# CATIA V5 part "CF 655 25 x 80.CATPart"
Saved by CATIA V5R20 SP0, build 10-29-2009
Part number: CF 655 25 x 80
Definition: NONE
Nomenclature: CF 655 25 x 80
Source: Unknown
Description: CF 655 25 x 80
Bounding box of the stored display mesh (mm): x -57 to 23, y -22 to 22, z -22 to 22
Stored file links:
  C:\Users\Utente\Desktop\IO LAVORO\3D X SITO CF\X SITO\CF 655\CF 655 25 x 80.CATPart
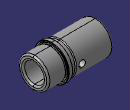
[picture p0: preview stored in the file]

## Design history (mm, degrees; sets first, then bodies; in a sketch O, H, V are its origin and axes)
Body1 "CF 655 25 x 80" (main body)
  Solid1: solid without history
